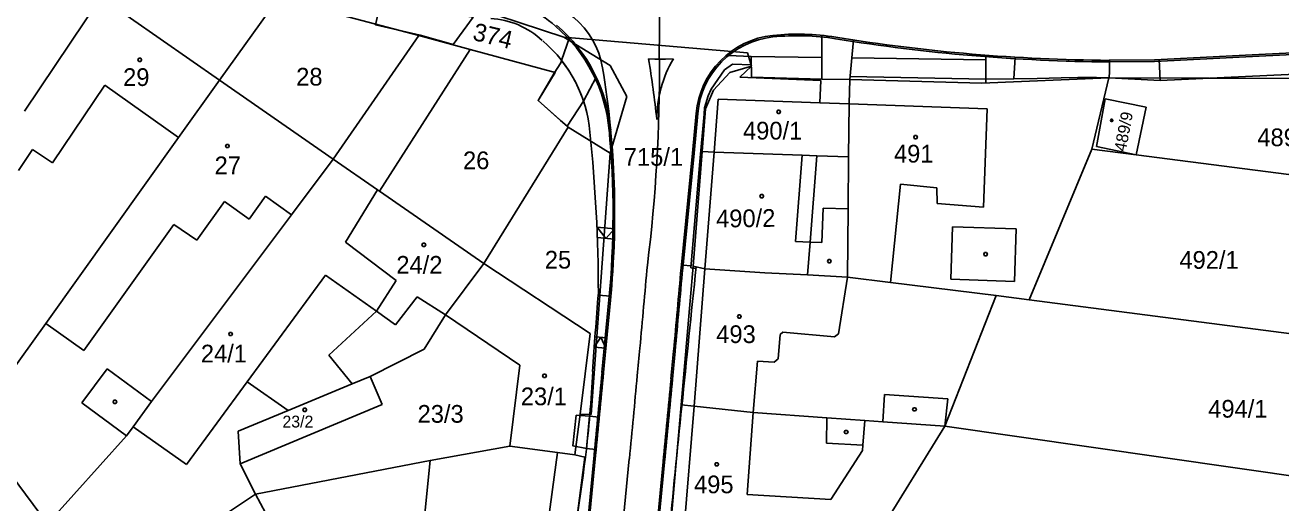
# Model space of a CAD drawing. Extents: x -639621 to -639329, y -1192893 to -1192488.
# Drawn here: x -639553.5 to -639433, y -1192770.8 to -1192724.9 of the extents above; entities that cross this region are included whole.
import ezdxf

# ---------------------------------------------------------------- set-up
doc = ezdxf.new("R2010")
doc.units = 0
for name, color, linetype in [('Vrstva 1', 7, 'Continuous'), ('Vrstva 19', 7, 'Continuous'), ('Vrstva 2', 7, 'Continuous'), ('Vrstva 20', 7, 'Continuous'), ('Vrstva 4', 7, 'Continuous'), ('Vrstva 5', 7, 'Continuous')]:
    doc.layers.add(name, color=color, linetype=linetype)

msp = doc.modelspace()

# ---------------------------------------------------------------- linework, layer by layer
at = {"layer": 'Vrstva 1'}
for p, q in [((-639546.26, -1192722.22), (-639553.6, -1192733.16)), ((-639529.26, -1192722.31), (-639534.88, -1192730.18)), ((-639515.75, -1192725.9), (-639529.26, -1192722.31)), ((-639512.37, -1192722.6), (-639501.84, -1192726.06)), ((-639515.75, -1192725.9), (-639523.97, -1192737.75)), ((-639510.81, -1192727.24), (-639515.75, -1192725.9)), ((-639501.84, -1192726.06), (-639484.21, -1192727.56)), ((-639501.84, -1192726.06), (-639497.38, -1192728.76)), ((-639519.51, -1192740.84), (-639510.81, -1192727.24)), ((-639502.67, -1192729.44), (-639510.81, -1192727.24)), ((-639483.84, -1192728.82), (-639484.21, -1192727.56)), ((-639504.3, -1192732.11), (-639502.67, -1192729.44)), ((-639497.38, -1192728.76), (-639495.79, -1192731.74)), ((-639485.89, -1192729.44), (-639487.46, -1192731.13)), ((-639483.84, -1192728.82), (-639485.89, -1192729.44)), ((-639484.96, -1192729.88), (-639483.84, -1192728.82)), ((-639538.8, -1192735.67), (-639534.88, -1192730.18)), ((-639534.88, -1192730.18), (-639523.97, -1192737.75)), ((-639477.18, -1192730.19), (-639484.96, -1192729.88)), ((-639477.27, -1192732.34), (-639477.18, -1192730.19)), ((-639474.39, -1192730.12), (-639474.46, -1192732.44)), ((-639461.71, -1192730.47), (-639474.39, -1192730.12)), ((-639449.52, -1192729.95), (-639461.71, -1192730.47)), ((-639451.15, -1192736.79), (-639449.52, -1192729.95)), ((-639449.52, -1192729.95), (-639428.21, -1192730.01)), ((-639501.41, -1192734.7), (-639504.3, -1192732.11)), ((-639495.79, -1192731.74), (-639497.4, -1192737.18)), ((-639487.46, -1192731.13), (-639488.23, -1192732.93)), ((-639449.89, -1192731.98), (-639450.7, -1192736.53)), ((-639445.94, -1192732.75), (-639449.89, -1192731.98)), ((-639488.23, -1192732.93), (-639488.56, -1192737.03)), ((-639474.46, -1192732.44), (-639477.27, -1192732.34)), ((-639474.51, -1192737.54), (-639474.46, -1192732.44)), ((-639446.92, -1192737.34), (-639445.94, -1192732.75)), ((-639551.56, -1192753.52), (-639538.8, -1192735.67)), ((-639509.52, -1192747.76), (-639501.41, -1192734.7)), ((-639501.41, -1192734.7), (-639497.4, -1192737.18)), ((-639457.18, -1192751.25), (-639451.15, -1192736.79)), ((-639446.92, -1192737.34), (-639451.15, -1192736.79)), ((-639450.7, -1192736.53), (-639446.92, -1192737.34)), ((-639523.97, -1192737.75), (-639527.96, -1192743.09)), ((-639497.4, -1192737.18), (-639499.22, -1192762.27)), ((-639488.56, -1192737.03), (-639489.43, -1192748.02)), ((-639488.56, -1192737.03), (-639487.41, -1192737.07)), ((-639478.97, -1192737.38), (-639487.41, -1192737.07)), ((-639477.57, -1192737.43), (-639478.97, -1192737.38)), ((-639478.21, -1192745.71), (-639477.57, -1192737.43)), ((-639474.56, -1192742.54), (-639474.51, -1192737.54)), ((-639420.45, -1192740.76), (-639446.92, -1192737.34)), ((-639519.72, -1192740.7), (-639522.79, -1192745.74)), ((-639519.72, -1192740.7), (-639519.51, -1192740.84)), ((-639519.51, -1192740.84), (-639509.52, -1192747.76)), ((-639474.62, -1192749.07), (-639474.56, -1192742.54)), ((-639527.96, -1192743.09), (-639541.39, -1192761.03)), ((-639522.79, -1192745.74), (-639517.92, -1192749.42)), ((-639478.46, -1192748.87), (-639478.21, -1192745.71)), ((-639509.52, -1192747.76), (-639513.18, -1192752.69)), ((-639499.31, -1192754.5), (-639509.52, -1192747.76)), ((-639489.43, -1192748.02), (-639490.57, -1192761.34)), ((-639489.43, -1192748.02), (-639488.29, -1192748.27)), ((-639488.29, -1192748.27), (-639482.55, -1192748.66)), ((-639482.55, -1192748.66), (-639478.46, -1192748.87)), ((-639478.46, -1192748.87), (-639474.62, -1192749.07)), ((-639517.92, -1192749.42), (-639519.82, -1192752.36)), ((-639474.62, -1192749.07), (-639470.47, -1192749.61)), ((-639470.47, -1192749.61), (-639460.35, -1192750.84)), ((-639460.35, -1192750.84), (-639465.28, -1192763.39)), ((-639460.35, -1192750.84), (-639457.18, -1192751.25)), ((-639422.16, -1192755.8), (-639457.18, -1192751.25)), ((-639519.82, -1192752.36), (-639524.38, -1192756.57)), ((-639558.48, -1192763.2), (-639551.56, -1192753.52)), ((-639513.18, -1192752.69), (-639515.24, -1192756.01)), ((-639506.05, -1192757.52), (-639513.18, -1192752.69)), ((-639500.28, -1192762.25), (-639499.31, -1192754.5)), ((-639515.24, -1192756.01), (-639520.41, -1192758.62)), ((-639522.14, -1192759.34), (-639524.38, -1192756.57)), ((-639520.41, -1192758.62), (-639522.14, -1192759.34)), ((-639520.41, -1192758.62), (-639519.26, -1192761.3)), ((-639507.01, -1192765.32), (-639506.05, -1192757.52)), ((-639538.04, -1192767.06), (-639532.22, -1192759.12)), ((-639532.22, -1192759.12), (-639528.29, -1192761.88)), ((-639522.14, -1192759.34), (-639528.29, -1192761.88)), ((-639541.39, -1192761.03), (-639543.16, -1192763.44)), ((-639528.29, -1192761.88), (-639533.09, -1192763.87)), ((-639519.26, -1192761.3), (-639532.89, -1192767.01)), ((-639500.77, -1192766.13), (-639500.28, -1192762.25)), ((-639499.22, -1192762.27), (-639500.28, -1192762.25)), ((-639490.57, -1192761.34), (-639491.69, -1192774.35)), ((-639489.32, -1192761.47), (-639490.57, -1192761.34)), ((-639489.32, -1192761.47), (-639483.65, -1192762.07)), ((-639476.6, -1192762.58), (-639483.65, -1192762.07)), ((-639551.4, -1192772.76), (-639558.48, -1192763.2)), ((-639543.16, -1192763.44), (-639543.8, -1192764.31)), ((-639543.16, -1192763.44), (-639538.04, -1192767.06)), ((-639472.96, -1192762.84), (-639476.6, -1192762.58)), ((-639473.03, -1192775.94), (-639465.28, -1192763.39)), ((-639471.23, -1192762.96), (-639472.96, -1192762.84)), ((-639465.28, -1192763.39), (-639471.23, -1192762.96)), ((-639423.61, -1192769.39), (-639465.28, -1192763.39)), ((-639543.8, -1192764.31), (-639551.4, -1192772.76)), ((-639532.89, -1192767.01), (-639533.09, -1192763.87)), ((-639507.01, -1192765.32), (-639514.66, -1192766.67)), ((-639502.43, -1192765.91), (-639507.01, -1192765.32)), ((-639531.42, -1192769.91), (-639532.89, -1192767.01)), ((-639514.66, -1192766.67), (-639531.42, -1192769.91)), ((-639504.82, -1192783.44), (-639502.43, -1192765.91)), ((-639500.77, -1192766.13), (-639502.43, -1192765.91)), ((-639501.61, -1192780.38), (-639499.83, -1192766.37)), ((-639499.83, -1192766.37), (-639500.77, -1192766.13)), ((-639531.42, -1192769.91), (-639544.66, -1192778.72)), ((-639528.64, -1192775.13), (-639531.42, -1192769.91))]:
    msp.add_line(p, q, dxfattribs=at)
at = {"layer": 'Vrstva 19'}
for p, q in [((-639492.59, -1192713.66), (-639492.67, -1192728.16)), ((-639492.66, -1192727.66), (-639492.66, -1192727.66)), ((-639453.38, -1192728.19), (-639453.39, -1192728.34)), ((-639492.67, -1192729.66), (-639492.67, -1192729.66)), ((-639489.48, -1192737.17), (-639489.14, -1192733.36)), ((-639489.48, -1192737.17), (-639490.58, -1192748.21)), ((-639497.77, -1192755.59), (-639497.37, -1192751.28)), ((-639498.78, -1192766.2), (-639502.89, -1192808.65)), ((-639492.31, -1192766.82), (-639496.42, -1192809.27))]:
    msp.add_line(p, q, dxfattribs=at)
for points in [[(-639449.51, -1192728.26), (-639445.16, -1192728.22), (-639436.4, -1192727.78), (-639431.89, -1192727.55), (-639421.13, -1192726.37), (-639420.39, -1192726.28)], [(-639491.33, -1192728.11), (-639492.67, -1192728.16), (-639493.71, -1192728.12)], [(-639495.55, -1192766.51), (-639499.66, -1192808.96)]]:
    msp.add_lwpolyline(points, dxfattribs=at)
for centre, radius, start, end in [((-639506.01, -1192730.3), 8, 9.4731, 90.8671), ((-639512.28, -1192736.29), 15, 4.9967, 49.491), ((-639480.91, -1192734.09), 8.26, 96.0371, 174.9645), ((-639479.38, -1192748.55), 22.8, 80.7841, 96.0371), ((-639448.08, -1192555.62), 172.66, 260.7841, 269.5265), ((-639643.94, -1192729.26), 151.28, 352.9129, 0.4151), ((-639581.96, -1192742.98), 89.5, 5.7986, 9.5552), ((-639492.59, -1192713.68), 14.49, 267.9968, 271.9808), ((-639480.91, -1192734.09), 12.01, 150.1314, 179.2539), ((-639581.96, -1192742.98), 85, 354.3936, 9.4731), ((-639581.96, -1192742.98), 85, 354.3936, 5.4805), ((-642481.96, -1192481.47), 3000, 354.75156, 354.90435), ((-642481.96, -1192481.47), 3003.25, 354.75156, 354.90435), ((-640988.13, -1192618.02), 1496.69, 354.6242, 354.7261), ((-640988.13, -1192618.02), 1499.94, 354.6242, 354.7261), ((-640988.13, -1192618.02), 1503.19, 354.6242, 354.7261), ((-642584.86, -1192466.24), 3100.62, 354.44848, 354.59619), ((-642584.86, -1192466.24), 3103.87, 354.44848, 354.59619), ((-642584.86, -1192466.24), 3107.12, 354.44848, 354.59619)]:
    msp.add_arc(centre, radius, start, end, dxfattribs=at)
at = {"layer": 'Vrstva 20'}
for p, q in [((-639502.05, -1192728.28), (-639501.29, -1192726.09)), ((-639477.09, -1192730.07), (-639477.09, -1192725.86)), ((-639474.39, -1192730.12), (-639474.03, -1192726.31)), ((-639483.86, -1192727.91), (-639486.02, -1192727.79)), ((-639483.82, -1192729.87), (-639483.86, -1192727.91)), ((-639477.09, -1192728), (-639483.86, -1192727.91)), ((-639461.34, -1192728.22), (-639474.19, -1192728.04)), ((-639461.34, -1192730.45), (-639461.34, -1192727.76)), ((-639458.66, -1192730.05), (-639458.53, -1192727.95)), ((-639449.48, -1192729.34), (-639449.48, -1192728.26)), ((-639444.59, -1192730.2), (-639444.69, -1192728.2)), ((-639487.71, -1192731.05), (-639486.41, -1192729.19)), ((-639486.41, -1192729.19), (-639485.65, -1192728.64)), ((-639485.65, -1192728.64), (-639483.84, -1192728.69)), ((-639449.48, -1192729.34), (-639449.49, -1192729.94)), ((-639444.59, -1192730.2), (-639430.08, -1192729.53)), ((-639499.95, -1192732.18), (-639498.72, -1192729.88)), ((-639477.09, -1192730.07), (-639483.82, -1192729.87)), ((-639474.39, -1192730.12), (-639477.09, -1192730.07)), ((-639461.34, -1192730.07), (-639474.38, -1192729.82)), ((-639449.49, -1192729.94), (-639444.59, -1192730.2)), ((-639488.32, -1192732.84), (-639487.98, -1192731.68)), ((-639487.98, -1192731.68), (-639487.71, -1192731.05)), ((-639488.37, -1192733.44), (-639488.32, -1192732.84)), ((-639489.33, -1192737.18), (-639488.99, -1192733.38)), ((-639488.77, -1192737.99), (-639488.37, -1192733.44)), ((-639489.33, -1192737.18), (-639490.43, -1192748.23)), ((-639489.65, -1192748.19), (-639488.77, -1192737.99)), ((-639498.65, -1192744.27), (-639496.98, -1192744.44)), ((-639498.65, -1192744.27), (-639497.81, -1192745.36)), ((-639498.61, -1192745.28), (-639497, -1192745.44)), ((-639497.81, -1192745.36), (-639496.98, -1192744.44)), ((-639489.63, -1192748), (-639490.4, -1192747.93)), ((-639489.15, -1192748.25), (-639489.65, -1192748.19)), ((-639498.53, -1192750.81), (-639497.34, -1192750.92)), ((-639497.92, -1192755.58), (-639497.52, -1192751.27)), ((-639498.27, -1192754.85), (-639498.91, -1192755.79)), ((-639498.84, -1192754.8), (-639497.71, -1192754.9)), ((-639497.8, -1192755.9), (-639498.27, -1192754.85)), ((-639498.91, -1192755.79), (-639497.8, -1192755.9)), ((-639499.36, -1192762.42), (-639498.43, -1192762.51)), ((-639499.68, -1192765.53), (-639498.73, -1192765.62)), ((-639498.93, -1192766.18), (-639503.04, -1192808.63)), ((-639492.17, -1192766.84), (-639496.27, -1192809.29))]:
    msp.add_line(p, q, dxfattribs=at)
for points in [[(-639519.36, -1192722.51), (-639519.9, -1192724.87), (-639515.62, -1192725.85), (-639512.47, -1192726.76), (-639510.54, -1192724.11), (-639511.38, -1192724), (-639512.46, -1192723.85), (-639514.11, -1192723.58), (-639515.89, -1192723.25), (-639517.76, -1192722.87)], [(-639499.36, -1192762.42), (-639500.65, -1192762.34), (-639500.97, -1192765.28), (-639499.66, -1192765.53)]]:
    msp.add_lwpolyline(points, close=True, dxfattribs=at)
for points in [[(-639449.5, -1192728.41), (-639445.15, -1192728.37), (-639436.39, -1192727.92), (-639431.88, -1192727.7), (-639421.11, -1192726.52), (-639420.37, -1192726.43)], [(-639502.05, -1192728.28), (-639502.13, -1192728.5), (-639502.75, -1192729.51), (-639504.3, -1192732.11), (-639502.15, -1192734.03), (-639501.53, -1192734.59), (-639499.95, -1192732.18)], [(-639501.44, -1192729.13), (-639502.05, -1192728.28)], [(-639461.34, -1192729.77), (-639461.34, -1192730.07), (-639458.66, -1192730.05)], [(-639458.66, -1192730.05), (-639456.4, -1192730.01), (-639454.1, -1192729.96), (-639452.52, -1192729.93), (-639451.57, -1192729.92), (-639450.71, -1192729.92), (-639449.49, -1192729.94)]]:
    msp.add_lwpolyline(points, dxfattribs=at)
for centre, radius, start, end in [((-639509.33, -1192732.23), 9.85, 47.2487, 86.6063), ((-639509.33, -1192732.23), 8, 47.2487, 86.6063), ((-639512.28, -1192736.29), 14.85, 4.9967, 49.491), ((-639480.91, -1192734.09), 8.11, 96.0371, 174.9645), ((-639479.38, -1192748.55), 22.65, 80.7841, 96.0371), ((-639512.28, -1192736.29), 13, 4.9967, 49.491), ((-639448.08, -1192555.62), 172.81, 260.7841, 269.5265), ((-639513.3, -1192736.86), 14.16, 25.8231, 33.1082), ((-639513.84, -1192736.92), 14.67, 18.8422, 25.0948), ((-639647.05, -1192750.75), 148.53, 0.0522, 6.0269), ((-639581.96, -1192742.98), 84.85, 354.3936, 5.4805), ((-642481.96, -1192481.47), 3003.4, 354.75156, 354.90435), ((-627942.69, -1193936.45), 11607.44, 174.123766, 174.190344), ((-639118.06, -1192782.23), 381.77, 175.251, 176.3835), ((-640988.13, -1192618.02), 1496.54, 354.6242, 354.7261), ((-640988.13, -1192618.02), 1503.34, 354.6242, 354.7261), ((-639637.29, -1192750.72), 138.43, 353.5154, 356.924), ((-642584.86, -1192466.24), 3100.47, 354.44848, 354.59619), ((-642584.86, -1192466.24), 3107.27, 354.44848, 354.59619), ((-638654.03, -1192849.48), 841.1, 173.99563, 175.72118), ((-637019, -1193111.1), 2504.59, 172.08826, 172.41402)]:
    msp.add_arc(centre, radius, start, end, dxfattribs=at)
at = {"layer": 'Vrstva 4'}
for p, q in [((-639546.26, -1192722.22), (-639534.88, -1192730.18)), ((-639545.9, -1192730.65), (-639550.91, -1192738.12)), ((-639538.8, -1192735.67), (-639545.9, -1192730.65)), ((-639487.02, -1192731.99), (-639487.41, -1192737.07)), ((-639477.27, -1192732.34), (-639487.02, -1192731.99)), ((-639461.21, -1192732.93), (-639474.46, -1192732.44)), ((-639461.21, -1192732.93), (-639461.57, -1192742.35)), ((-639554.18, -1192738.84), (-639552.83, -1192736.83)), ((-639550.91, -1192738.12), (-639552.83, -1192736.83)), ((-639523.97, -1192737.75), (-639519.72, -1192740.7)), ((-639487.41, -1192737.07), (-639488.29, -1192748.27)), ((-639478.97, -1192737.38), (-639479.61, -1192745.66)), ((-639477.57, -1192737.43), (-639474.51, -1192737.54)), ((-639470.47, -1192749.61), (-639469.51, -1192740.17)), ((-639469.51, -1192740.17), (-639466.04, -1192740.52)), ((-639466.04, -1192740.52), (-639466, -1192742)), ((-639530.45, -1192741.31), (-639532.03, -1192743.51)), ((-639527.96, -1192743.09), (-639530.45, -1192741.31)), ((-639534.41, -1192741.81), (-639537.06, -1192745.52)), ((-639532.03, -1192743.51), (-639534.41, -1192741.81)), ((-639476.96, -1192742.45), (-639477.08, -1192745.75)), ((-639474.56, -1192742.54), (-639476.96, -1192742.45)), ((-639466, -1192742), (-639461.57, -1192742.35)), ((-639539.25, -1192744.04), (-639547.89, -1192756.14)), ((-639537.06, -1192745.52), (-639539.25, -1192744.04)), ((-639464.7, -1192749.28), (-639464.52, -1192744.24)), ((-639464.52, -1192744.24), (-639458.41, -1192744.46)), ((-639458.59, -1192749.49), (-639458.41, -1192744.46)), ((-639479.61, -1192745.66), (-639478.21, -1192745.71)), ((-639478.21, -1192745.71), (-639477.08, -1192745.75)), ((-639532.22, -1192759.12), (-639524.71, -1192748.9)), ((-639524.71, -1192748.9), (-639519.82, -1192752.36)), ((-639488.29, -1192748.27), (-639489.32, -1192761.47)), ((-639475.47, -1192754.52), (-639474.62, -1192749.07)), ((-639464.7, -1192749.28), (-639458.59, -1192749.49)), ((-639515.91, -1192750.96), (-639517.98, -1192753.67)), ((-639513.18, -1192752.69), (-639515.91, -1192750.96)), ((-639519.82, -1192752.36), (-639517.98, -1192753.67)), ((-639547.89, -1192756.14), (-639551.56, -1192753.52)), ((-639481.27, -1192756.93), (-639481.08, -1192754.59)), ((-639481.08, -1192754.59), (-639480.81, -1192754.36)), ((-639480.81, -1192754.36), (-639475.85, -1192754.82)), ((-639475.85, -1192754.82), (-639475.47, -1192754.52)), ((-639483.65, -1192762.07), (-639483.25, -1192757.16)), ((-639483.25, -1192757.16), (-639481.64, -1192757.26)), ((-639481.64, -1192757.26), (-639481.27, -1192756.93)), ((-639545.66, -1192757.87), (-639548.08, -1192761.14)), ((-639541.39, -1192761.03), (-639545.66, -1192757.87)), ((-639471.23, -1192762.96), (-639471.07, -1192760.35)), ((-639471.07, -1192760.35), (-639464.98, -1192760.78)), ((-639464.98, -1192760.78), (-639465.28, -1192763.39)), ((-639543.8, -1192764.31), (-639548.08, -1192761.14)), ((-639490.4, -1192774.46), (-639489.32, -1192761.47)), ((-639484.24, -1192769.96), (-639483.65, -1192762.07)), ((-639476.6, -1192762.58), (-639476.63, -1192765.03)), ((-639472.96, -1192762.84), (-639473.14, -1192765.21)), ((-639476.63, -1192765.03), (-639473.14, -1192765.21)), ((-639476.21, -1192770.44), (-639473.18, -1192765.74)), ((-639473.18, -1192765.74), (-639473.14, -1192765.21)), ((-639514.66, -1192766.67), (-639515.25, -1192772.42)), ((-639484.24, -1192769.96), (-639476.21, -1192770.44))]:
    msp.add_line(p, q, dxfattribs=at)
at = {"layer": 'Vrstva 5'}
for points in [[(-639542.44, -1192728.07), (-639542.35, -1192728.22), (-639542.44, -1192728.37), (-639542.62, -1192728.37), (-639542.71, -1192728.22), (-639542.62, -1192728.07)], [(-639481.13, -1192733.06), (-639481.04, -1192733.21), (-639481.13, -1192733.36), (-639481.31, -1192733.36), (-639481.4, -1192733.21), (-639481.31, -1192733.06)], [(-639449.2, -1192733.93), (-639449.14, -1192734.03), (-639449.2, -1192734.13), (-639449.32, -1192734.13), (-639449.38, -1192734.03), (-639449.32, -1192733.93)], [(-639467.99, -1192735.49), (-639467.9, -1192735.64), (-639467.99, -1192735.79), (-639468.17, -1192735.79), (-639468.26, -1192735.64), (-639468.17, -1192735.49)], [(-639534.03, -1192736.35), (-639533.94, -1192736.5), (-639534.03, -1192736.65), (-639534.21, -1192736.65), (-639534.3, -1192736.5), (-639534.21, -1192736.35)], [(-639482.75, -1192741.16), (-639482.66, -1192741.31), (-639482.75, -1192741.46), (-639482.93, -1192741.46), (-639483.02, -1192741.31), (-639482.93, -1192741.16)], [(-639515.18, -1192745.83), (-639515.09, -1192745.98), (-639515.18, -1192746.13), (-639515.36, -1192746.13), (-639515.45, -1192745.98), (-639515.36, -1192745.83)], [(-639476.27, -1192747.4), (-639476.18, -1192747.55), (-639476.27, -1192747.7), (-639476.45, -1192747.7), (-639476.54, -1192747.55), (-639476.45, -1192747.4)], [(-639461.27, -1192746.73), (-639461.18, -1192746.88), (-639461.27, -1192747.03), (-639461.45, -1192747.03), (-639461.54, -1192746.88), (-639461.45, -1192746.73)], [(-639484.9, -1192752.71), (-639484.81, -1192752.86), (-639484.9, -1192753.01), (-639485.08, -1192753.01), (-639485.17, -1192752.86), (-639485.08, -1192752.71)], [(-639533.73, -1192754.4), (-639533.64, -1192754.55), (-639533.73, -1192754.7), (-639533.91, -1192754.7), (-639534, -1192754.55), (-639533.91, -1192754.4)], [(-639503.6, -1192758.41), (-639503.51, -1192758.56), (-639503.6, -1192758.71), (-639503.78, -1192758.71), (-639503.87, -1192758.56), (-639503.78, -1192758.41)], [(-639544.83, -1192760.9), (-639544.74, -1192761.05), (-639544.83, -1192761.2), (-639545.01, -1192761.2), (-639545.1, -1192761.05), (-639545.01, -1192760.9)], [(-639526.61, -1192761.67), (-639526.52, -1192761.82), (-639526.61, -1192761.97), (-639526.79, -1192761.97), (-639526.88, -1192761.82), (-639526.79, -1192761.67)], [(-639468.09, -1192761.63), (-639468, -1192761.78), (-639468.09, -1192761.93), (-639468.27, -1192761.93), (-639468.36, -1192761.78), (-639468.27, -1192761.63)], [(-639474.65, -1192763.8), (-639474.56, -1192763.95), (-639474.65, -1192764.1), (-639474.83, -1192764.1), (-639474.92, -1192763.95), (-639474.83, -1192763.8)], [(-639487.07, -1192766.9), (-639486.98, -1192767.05), (-639487.07, -1192767.2), (-639487.25, -1192767.2), (-639487.34, -1192767.05), (-639487.25, -1192766.9)]]:
    msp.add_lwpolyline(points, close=True, dxfattribs=at)

# ---------------------------------------------------------------- texts
at = {"layer": 'Vrstva 2'}
for s, height, rotation, p in [('374', 1.7, 346.2091, (-639510.68, -1192726.29)), ('489/9', 1.14, 79.2974, (-639447.91, -1192737.08)), ('490/2', 1.7, 0.7448, (-639487.21, -1192744.32))]:
    msp.add_text(s, height=height, rotation=rotation, dxfattribs=at).set_placement(p)
for s, height, p in [('29', 1.7, (-639544.13, -1192730.73)), ('28', 1.7, (-639527.52, -1192730.69)), ('490/1', 1.7, (-639484.64, -1192735.87)), ('489/1', 1.7, (-639435.28, -1192736.51)), ('715/1', 1.7, (-639496.08, -1192738.39)), ('491', 1.7, (-639470.15, -1192738.08)), ('27', 1.7, (-639535.35, -1192739.2)), ('26', 1.7, (-639511.51, -1192738.72)), ('25', 1.7, (-639503.66, -1192748.26)), ('492/1', 1.7, (-639442.76, -1192748.28)), ('24/2', 1.7, (-639517.91, -1192748.75)), ('493', 1.7, (-639487.21, -1192755.41)), ('24/1', 1.7, (-639536.67, -1192757.27)), ('23/1', 1.7, (-639505.96, -1192761.38)), ('494/1', 1.7, (-639439.99, -1192762.57)), ('23/3', 1.7, (-639515.87, -1192763.06)), ('23/2', 1.14, (-639528.84, -1192763.52)), ('495', 1.7, (-639489.34, -1192769.83))]:
    msp.add_text(s, height=height, dxfattribs=at).set_placement(p)

doc.saveas('drawing.dxf')
